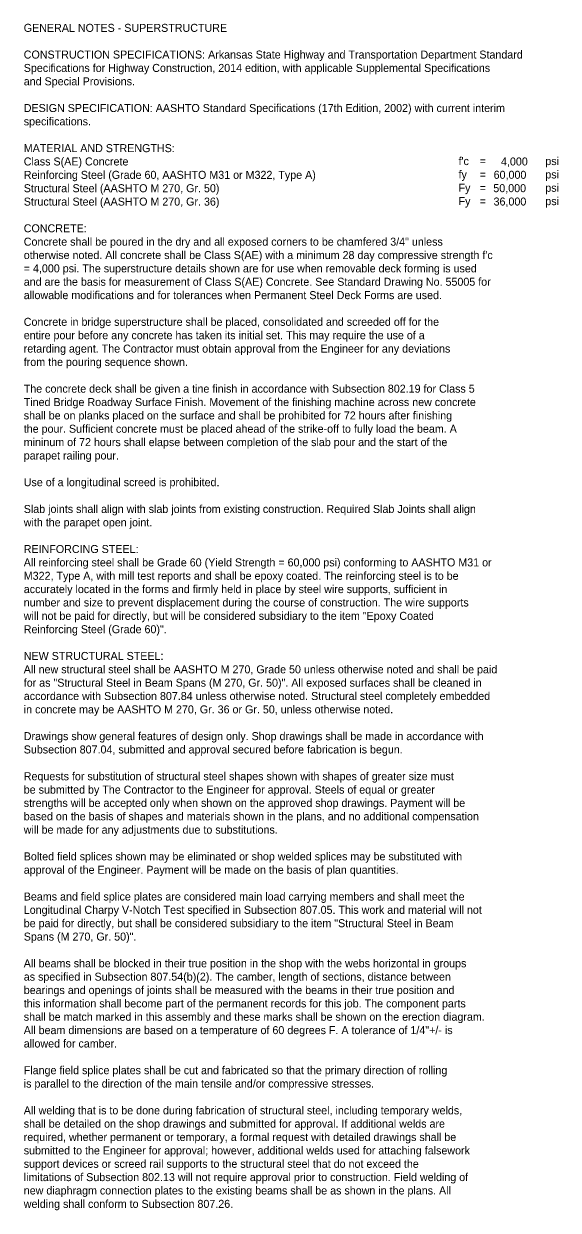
# Model space of a CAD drawing. Extents: x -30245.5 to -30215.1, y 5204.9 to 5224.7.
# Drawn here: x -30245.5 to -30237.15, y 5206.12 to 5224.66 of the extents above; entities that cross this region are included whole.
import ezdxf

# ---------------------------------------------------------------- set-up
doc = ezdxf.new("R2010")
doc.units = 0
doc.layers.add('B_Text', color=7, linetype='Continuous')

msp = doc.modelspace()

# ---------------------------------------------------------------- texts
at = {"layer": 'B_Text'}
for s, p in [('GENERAL NOTES - SUPERSTRUCTURE', (-30245.501, 5224.529)), ('CONSTRUCTION SPECIFICATIONS: Arkansas State Highway and Transportation Department Standard ', (-30245.501, 5224.112)), ('Specifications for Highway Construction, 2014 edition, with applicable Supplemental Specifications ', (-30245.501, 5223.903)), ('and Special Provisions.', (-30245.501, 5223.694)), ('DESIGN SPECIFICATION: AASHTO Standard Specifications (17th Edition, 2002) with current interim ', (-30245.501, 5223.277)), ('specifications.', (-30245.501, 5223.068)), ('MATERIAL AND STRENGTHS:', (-30245.501, 5222.65)), ('Class S(AE) Concrete', (-30245.501, 5222.442)), ("f'c", (-30238.71, 5222.448)), ('=', (-30238.379, 5222.448)), ('4,000', (-30238.047, 5222.442)), ('psi', (-30237.355, 5222.448)), ('Reinforcing Steel (Grade 60, AASHTO M31 or M322, Type A)', (-30245.501, 5222.233)), ('fy', (-30238.71, 5222.239)), ('=', (-30238.379, 5222.239)), ('60,000', (-30238.162, 5222.234)), ('psi', (-30237.355, 5222.239)), ('Structural Steel (AASHTO M 270, Gr. 50)', (-30245.501, 5222.024)), ('Fy', (-30238.71, 5222.031)), ('=', (-30238.379, 5222.031)), ('50,000', (-30238.167, 5222.025)), ('psi', (-30237.355, 5222.031)), ('Structural Steel (AASHTO M 270, Gr. 36)', (-30245.501, 5221.815)), ('Fy', (-30238.71, 5221.822)), ('36,000', (-30238.163, 5221.816)), ('psi', (-30237.355, 5221.822)), ('=', (-30238.379, 5221.822)), ('CONCRETE:', (-30245.501, 5221.398)), ('Concrete shall be poured in the dry and all exposed corners to be chamfered 3/4" unless ', (-30245.501, 5221.189)), ("otherwise noted. All concrete shall be Class S(AE) with a minimum 28 day compressive strength f'c ", (-30245.501, 5220.98)), ('= 4,000 psi. The superstructure details shown are for use when removable deck forming is used ', (-30245.501, 5220.772)), ('and are the basis for measurement of Class S(AE) Concrete. See Standard Drawing No. 55005 for ', (-30245.501, 5220.563)), ('allowable modifications and for tolerances when Permanent Steel Deck Forms are used.', (-30245.501, 5220.354)), ('Concrete in bridge superstructure shall be placed, consolidated and screeded off for the ', (-30245.501, 5219.937)), ('entire pour before any concrete has taken its initial set. This may require the use of a ', (-30245.501, 5219.728)), ('retarding agent. The Contractor must obtain approval from the Engineer for any deviations ', (-30245.501, 5219.519)), ('from the pouring sequence shown.', (-30245.501, 5219.31)), ('The concrete deck shall be given a tine finish in accordance with Subsection 802.19 for Class 5 ', (-30245.501, 5218.893)), ('Tined Bridge Roadway Surface Finish. Movement of the finishing machine across new concrete ', (-30245.501, 5218.684)), ('shall be on planks placed on the surface and shall be prohibited for 72 hours after finishing ', (-30245.501, 5218.475)), ('the pour. Sufficient concrete must be placed ahead of the strike-off to fully load the beam. A ', (-30245.501, 5218.267)), ('mininum of 72 hours shall elapse between completion of the slab pour and the start of the ', (-30245.501, 5218.058)), ('parapet railing pour.', (-30245.501, 5217.849)), ('Use of a longitudinal screed is prohibited.', (-30245.501, 5217.432)), ('Slab joints shall align with slab joints from existing construction. Required Slab Joints shall align ', (-30245.501, 5217.014)), ('with the parapet open joint.', (-30245.501, 5216.805)), ('REINFORCING STEEL:', (-30245.501, 5216.388)), ('All reinforcing steel shall be Grade 60 (Yield Strength = 60,000 psi) conforming to AASHTO M31 or ', (-30245.501, 5216.179)), ('M322, Type A, with mill test reports and shall be epoxy coated. The reinforcing steel is to be ', (-30245.501, 5215.97)), ('accurately located in the forms and firmly held in place by steel wire supports, sufficient in ', (-30245.501, 5215.762)), ('number and size to prevent displacement during the course of construction. The wire supports ', (-30245.501, 5215.553)), ('will not be paid for directly, but will be considered subsidiary to the item "Epoxy Coated ', (-30245.501, 5215.344)), ('Reinforcing Steel (Grade 60)".', (-30245.501, 5215.135)), ('NEW STRUCTURAL STEEL:', (-30245.501, 5214.718)), ('All new structural steel shall be AASHTO M 270, Grade 50 unless otherwise noted and shall be paid ', (-30245.501, 5214.509)), ('for as "Structural Steel in Beam Spans (M 270, Gr. 50)". All exposed surfaces shall be cleaned in ', (-30245.501, 5214.3)), ('accordance with Subsection 807.84 unless otherwise noted. Structural steel completely embedded ', (-30245.501, 5214.092)), ('in concrete may be AASHTO M 270, Gr. 36 or Gr. 50, unless otherwise noted.', (-30245.501, 5213.883)), ('Drawings show general features of design only. Shop drawings shall be made in accordance with ', (-30245.501, 5213.465)), ('Subsection 807.04, submitted and approval secured before fabrication is begun.', (-30245.501, 5213.257)), ('Requests for substitution of structural steel shapes shown with shapes of greater size must ', (-30245.501, 5212.839)), ('be submitted by The Contractor to the Engineer for approval. Steels of equal or greater ', (-30245.501, 5212.63)), ('strengths will be accepted only when shown on the approved shop drawings. Payment will be ', (-30245.501, 5212.422)), ('based on the basis of shapes and materials shown in the plans, and no additional compensation ', (-30245.501, 5212.213)), ('will be made for any adjustments due to substitutions.', (-30245.501, 5212.004)), ('Bolted field splices shown may be eliminated or shop welded splices may be substituted with ', (-30245.501, 5211.587)), ('approval of the Engineer. Payment will be made on the basis of plan quantities.', (-30245.501, 5211.378)), ('Beams and field splice plates are considered main load carrying members and shall meet the ', (-30245.501, 5210.96)), ('Longitudinal Charpy V-Notch Test specified in Subsection 807.05. This work and material will not ', (-30245.501, 5210.752)), ('be paid for directly, but shall be considered subsidiary to the item "Structural Steel in Beam ', (-30245.501, 5210.543)), ('Spans (M 270, Gr. 50)".', (-30245.501, 5210.334)), ('All beams shall be blocked in their true position in the shop with the webs horizontal in groups ', (-30245.501, 5209.917)), ('as specified in Subsection 807.54(b)(2). The camber, length of sections, distance between ', (-30245.501, 5209.708)), ('bearings and openings of joints shall be measured with the beams in their true position and ', (-30245.501, 5209.499)), ('this information shall become part of the permanent records for this job. The component parts ', (-30245.501, 5209.29)), ('shall be match marked in this assembly and these marks shall be shown on the erection diagram. ', (-30245.501, 5209.082)), ('All beam dimensions are based on a temperature of 60 degrees F. A tolerance of 1/4"+/- is ', (-30245.501, 5208.873)), ('allowed for camber.', (-30245.501, 5208.664)), ('Flange field splice plates shall be cut and fabricated so that the primary direction of rolling ', (-30245.501, 5208.247)), ('is parallel to the direction of the main tensile and/or compressive stresses.', (-30245.501, 5208.038)), ('All welding that is to be done during fabrication of structural steel, including temporary welds, ', (-30245.501, 5207.62)), ('shall be detailed on the shop drawings and submitted for approval. If additional welds are ', (-30245.501, 5207.412)), ('required, whether permanent or temporary, a formal request with detailed drawings shall be ', (-30245.501, 5207.203)), ('submitted to the Engineer for approval; however, additional welds used for attaching falsework ', (-30245.501, 5206.994)), ('support devices or screed rail supports to the structural steel that do not exceed the ', (-30245.501, 5206.785)), ('limitations of Subsection 802.13 will not require approval prior to construction. Field welding of ', (-30245.501, 5206.577)), ('new diaphragm connection plates to the existing beams shall be as shown in the plans. All ', (-30245.501, 5206.368)), ('welding shall conform to Subsection 807.26.', (-30245.501, 5206.159))]:
    msp.add_text(s, height=0.125, dxfattribs=at).set_placement(p)

doc.saveas('drawing.dxf')
